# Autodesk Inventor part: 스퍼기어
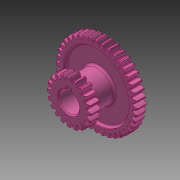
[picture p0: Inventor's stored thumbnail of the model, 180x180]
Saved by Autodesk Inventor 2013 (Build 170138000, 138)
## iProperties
Created: 2015-09
Part Number: 스퍼기어
Material: 강철, 연강
Document SubType Name: Modeling
Designer: mduedu
Density: 7.86 g/cm^3
Mass: 345.726 g
Surface Area: 225.641 cm^2
Volume: 43.9855 cm^3
Author: mduedu
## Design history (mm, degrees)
sketch "스케치1"
  geometry: C1 r 38 at (0, 0); C2 r 40 at (0, 0); C3 r 35.5 at (0, 0); 1 further point
  constraints: 3 centre point, 3 coincident
  dimensions: "d0" = 76 diameter of C1; "d2" = 2 radial gap between concentric circles of C2 C1; "d3" = 71 diameter of C3 (computed from d0)
extrude "돌출1" new body sketch "스케치1" stored distance "d4" = 10; taper "d5" = 0 deg
sketch "스케치2"
  geometry: L1 (0, 35.5)-(0, -35.5); L2 (0, 0)-(40, 0); L3 (0, 0.57)-(39.996, 0.57); L4 (0, 1.57)-(39.969, 1.57); L5 (0, 2.07)-(39.946, 2.07); A1 r 35.5 centre (0, 0) between (0, 35.5) and (0, -35.5) reference; A2 r 40 centre (0, 0) between (40, 0) and (39.946, 2.07) reference; A3 r 9.234 centre (34.93, -7.149) between (39.996, 0.57) and (35.44, 2.07); A4 r 9.234 centre (34.93, 7.149) between (35.44, -2.07) and (39.996, -0.57); A5 r 40 centre (0, 0) between (39.996, -0.57) and (39.996, 0.57); A6 r 35.5 centre (0, 0) between (35.44, -2.07) and (35.44, 2.07); 4 further points
  constraints: 16 point on circle, 10 end point, 6 point on line, 4 centre point, 3 coincident, 3 parallel, 3 symmetric about line, 2 midpoint, 1 perpendicular, 1 vertical, 3 other
  dimensions: "d6" = 0.5 distance between parallel lines of L4 L5; "d8" = 1 distance between parallel lines of L3 L4; "d9" = 1.57 distance between parallel lines of L2 L4
extrude "돌출2" join sketch "스케치2" distance "d10" = 5; taper "d12" = 0 deg; dims "d11" = 5, "d13" = 0
fillet "모깎기1" dims "d17" = 0.5
chamfer "모따기1" distance "d21" = 1; stored, may be unused: second distance "d22" = 2, angle "d23" = 45 deg
sketch "스케치3"
  geometry: C1 r 32.5 at (0, 0); C2 r 15 at (0, 0); 1 further point
  constraints: 2 centre point, 2 coincident
  dimensions: "d27" = 65 diameter of C1; "d28" = 30 diameter of C2
extrude "돌출3" cut sketch "스케치3" distance "d29" = 3; taper "d30" = 0 deg
fillet "모깎기2" dims "d31" = 2
node "작업 평면2"
  node "작업 평면1"
sketch "스케치4"
  geometry: C1 r 15 at (0, 0) reference; 1 further point
extrude "돌출4" join sketch "스케치4" stored distance "d34" = 3; taper "d35" = 0 deg
sketch "스케치5"
  geometry: C1 r 17.5 at (0, 0); C2 r 20 at (0, 0); C3 r 22 at (0, 0); 1 further point
  constraints: 3 centre point, 3 coincident
  dimensions: "d36" = 40 diameter of C2; "d38" = 2 radial gap between concentric circles of C2 C3; "d39" = 35 diameter of C1 (= d36 - 2.5 x d38)
extrude "돌출6" join sketch "스케치5" distance "d46" = 10; taper "d47" = 0 deg
sketch "스케치6"
  geometry: L1 (0, 0)-(0, 22); L2 (-17.5, 0)-(17.5, 0); L3 (-0.57, 0)-(-0.57, 21.993); L4 (-1.57, 0)-(-1.57, 21.944); L5 (-2.07, 0)-(-2.07, 21.902); A1 r 22 centre (0, 0) between (0, 22) and (-0.57, 21.993) reference; A2 r 17.5 centre (0, 0) between (-17.5, 0) and (17.5, 0) reference; A3 r 9.431 centre (7.348, 16.868) between (-0.57, 21.993) and (-2.07, 17.377); A4 r 9.431 centre (-7.348, 16.868) between (2.07, 17.377) and (0.57, 21.993); A5 r 17.5 centre (0, 0) between (2.07, 17.377) and (-2.07, 17.377); A6 r 22 centre (0, 0) between (0.57, 21.993) and (-0.57, 21.993); 4 further points
  constraints: 16 point on circle, 10 end point, 5 point on line, 4 centre point, 3 coincident, 3 symmetric about line, 2 parallel, 2 perpendicular, 1 midpoint, 1 vertical, 3 other
  dimensions: "d40" = 0.5 distance between parallel lines of L4 L5; "d42" = 1 distance between parallel lines of L3 L4; "d43" = 1.57 distance between parallel lines of L1 L4
extrude "돌출5" join sketch "스케치6" distance "d44" = 10; taper "d45" = 0 deg
fillet "모깎기3" dims "d48" = 0.5
chamfer "모따기2" distance "d49" = 1; stored, may be unused: second distance "d50" = 2, angle "d51" = 45 deg
sketch "스케치7"
  geometry: C1 r 10 at (0, 0); 1 further point
  constraints: 1 centre point, 1 coincident
  dimensions: "d55" = 20 diameter of C1
extrude "돌출7" cut sketch "스케치7" stored distance "d56" = 10; taper "d57" = 0 deg
sketch "스케치8"
  geometry: L1 (-9.539, -3)-(-12.8, -3); L2 (-12.8, -3)-(-12.8, 3); L3 (-12.8, 3)-(-9.539, 3); L4 (-9.539, 3)-(-9.539, -3); A1 r 10 centre (0, 0) between (-9.539, -3) and (-9.539, 3) reference; 2 further points
  constraints: 8 end point, 3 point on circle, 2 parallel, 1 horizontal, 1 horizontal alignment, 1 perpendicular
  dimensions: "d58" = 6 distance of L1.end L2.end; "d60" = 22.8 distance from line of point (10, 0) L2
extrude "돌출8" cut sketch "스케치8" stored distance "d61" = 10; taper "d62" = 0 deg
chamfer "모따기3" distance "d63" = 1; stored, may be unused: second distance "d64" = 2, angle "d65" = 45 deg
fillet "모깎기4" dims "d66" = 2
node "솔리드1"
pattern_circular "원형 패턴3" dims "d25" = 360 deg
mirror "대칭1"
pattern_circular "원형 패턴4" dims "d53" = 360 deg
other parameters: "d32" = 5, "d33" = 42
